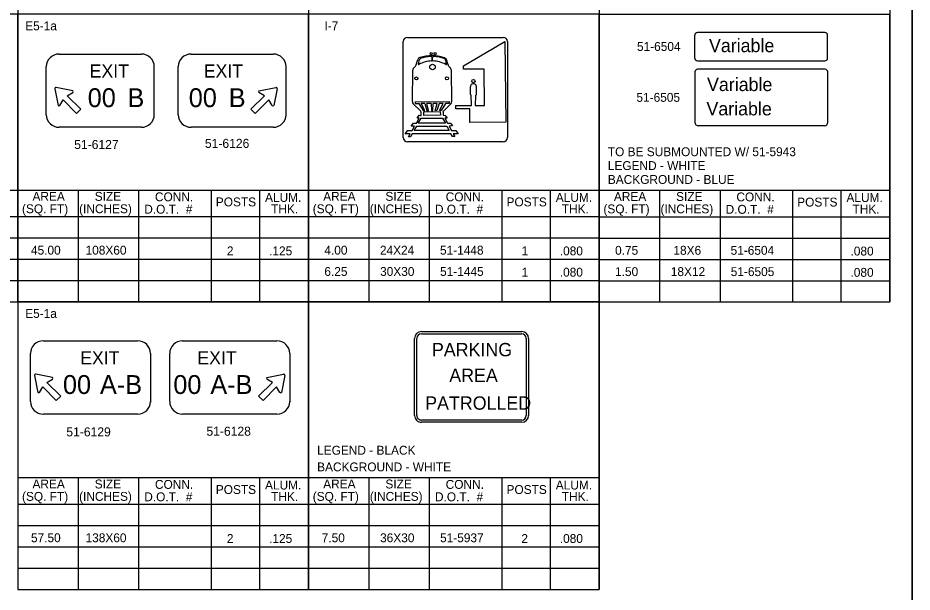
# Model space of a CAD drawing. Extents: x 0 to 2011, y -71 to 1183.
# Drawn here: x 947.8 to 1270, y 392.2 to 599.1 of the extents above; entities that cross this region are included whole.
import ezdxf

# ---------------------------------------------------------------- set-up
doc = ezdxf.new("R2010")
doc.units = 0
for name, color, linetype in [('CT_Border_Perimeter_Shape', 7, 'Continuous'), ('CT_Construction', 7, 'Continuous'), ('Level 1', 7, 'Continuous'), ('Level 2', 7, 'Continuous'), ('Level 5', 7, 'Continuous')]:
    doc.layers.add(name, color=color, linetype=linetype)

msp = doc.modelspace()

# ---------------------------------------------------------------- linework, layer by layer
at = {"layer": 'CT_Border_Perimeter_Shape'}
msp.add_lwpolyline([(0, -0.97), (1270, -0.97), (1270, 829.03), (0, 829.03)], close=True, dxfattribs=at)
at = {"layer": 'CT_Construction'}
msp.add_lwpolyline([(0, 829.03), (1270, 829.03), (1270, 59.03), (0, 59.03)], close=True, dxfattribs=at)
at = {"layer": 'Level 1'}
for p, q in [((1238.58, 593.82), (1192.65, 593.82)), ((1086.58, 556), (1086.58, 590.55)), ((1088.13, 592.1), (1122.68, 592.1)), ((1124.23, 590.55), (1124.23, 556)), ((1191.68, 584.63), (1191.68, 592.86)), ((1239.54, 584.63), (1239.54, 592.86)), ((962.59, 586.1), (992.27, 586.1)), ((1010.09, 586.1), (1039.77, 586.1)), ((1091.25, 582.22), (1091.84, 584.12)), ((1097.01, 583.77), (1097.02, 584.85)), ((1097.24, 583.77), (1097.23, 584.85)), ((1102.79, 582.19), (1102.2, 584.09)), ((1192.65, 583.67), (1238.58, 583.67)), ((958.02, 564.24), (958.02, 581.56)), ((996.94, 564.24), (996.94, 581.56)), ((1005.53, 564.24), (1005.53, 581.56)), ((1044.45, 564.24), (1044.45, 581.56)), ((1238.65, 580.59), (1192.72, 580.59)), ((1191.75, 579.62), (1191.75, 561.48)), ((1239.61, 561.48), (1239.61, 579.62)), ((961.05, 573.58), (962.26, 567.54)), ((967.57, 572.86), (961.54, 574.07)), ((1034.66, 572.86), (1040.69, 574.07)), ((1041.18, 573.58), (1039.98, 567.54)), ((965.54, 571.06), (967.57, 572.27)), ((970.5, 566.21), (965.54, 571.06)), ((1031.73, 566.21), (1036.7, 571.06)), ((1036.7, 571.06), (1034.66, 572.27)), ((962.85, 567.54), (964.06, 569.58)), ((964.06, 569.58), (968.9, 564.62)), ((1038.17, 569.58), (1033.33, 564.62)), ((1039.39, 567.54), (1038.17, 569.58)), ((1101.13, 565.56), (1103.78, 568.1)), ((968.9, 564.62), (970.5, 566.21)), ((1033.33, 564.62), (1031.73, 566.21)), ((1100.97, 565.12), (1101.01, 565.34)), ((1101.01, 565.34), (1101.13, 565.56)), ((992.27, 559.7), (962.69, 559.7)), ((1039.77, 559.7), (1010.2, 559.7)), ((1238.4, 560.27), (1192.96, 560.27)), ((1122.68, 554.45), (1088.13, 554.45)), ((1089.3, 556.23), (1088.5, 556.23)), ((1090.71, 455.87), (1090.71, 483.65)), ((1091.52, 455.87), (1091.52, 483.65)), ((1093.18, 486.11), (1129.32, 486.11)), ((1093.18, 485.31), (1129.32, 485.31)), ((1130.98, 483.65), (1130.98, 455.87)), ((1131.79, 483.65), (1131.79, 455.87)), ((956.86, 482.76), (986.55, 482.76)), ((956.86, 482.76), (990.9, 482.76)), ((1007.04, 482.76), (1036.73, 482.76)), ((1007.04, 482.76), (1041.09, 482.76)), ((952.3, 460.89), (952.3, 478.22)), ((995.57, 478.22), (995.57, 460.6)), ((1002.48, 460.89), (1002.48, 478.22)), ((1045.76, 478.22), (1045.76, 460.6)), ((960.29, 469.52), (954.25, 470.73)), ((1037.45, 469.52), (1043.49, 470.73)), ((953.76, 470.24), (954.97, 464.2)), ((958.25, 467.72), (960.29, 468.93)), ((963.21, 462.87), (958.25, 467.72)), ((1034.53, 462.87), (1039.49, 467.72)), ((1039.49, 467.72), (1037.45, 468.93)), ((1043.98, 470.24), (1042.77, 464.2)), ((955.56, 464.2), (956.77, 466.24)), ((956.77, 466.24), (961.62, 461.28)), ((1040.97, 466.24), (1036.12, 461.28)), ((1042.18, 464.2), (1040.97, 466.24)), ((961.62, 461.28), (963.21, 462.87)), ((1036.12, 461.28), (1034.53, 462.87)), ((990.9, 456.36), (956.97, 456.36)), ((1041.09, 456.36), (1007.15, 456.36)), ((1129.32, 454.21), (1093.18, 454.21)), ((1129.32, 453.41), (1093.18, 453.41))]:
    msp.add_line(p, q, dxfattribs=at)
for points in [[(1112.68, 571.19), (1112.57, 567.56), (1115.86, 567.56), (1115.79, 580.59), (1108.34, 580.58), (1108.37, 581.82), (1123.21, 590.65), (1123.57, 561.59)], [(1089.94, 568.98), (1090.05, 580.26)], [(1104.1, 568.95), (1103.99, 580.23)], [(1110.84, 571.52), (1110.85, 574.33)], [(1113, 571.48), (1112.99, 574.29)], [(1123.57, 561.59), (1110.63, 561.45), (1110.6, 566.39), (1105.57, 566.34), (1105.58, 567.49), (1111.29, 567.57), (1111.16, 571.24)], [(1088.5, 556.23), (1089.14, 557.31), (1087.38, 557.33), (1088.3, 558.52), (1089.85, 558.52), (1090.74, 560.13), (1089.54, 560.13), (1090.35, 561.21), (1091.42, 561.18), (1092.37, 562.95), (1091.67, 562.97), (1092.41, 564.01), (1092.89, 564), (1093.05, 564), (1093.07, 565.15), (1093.03, 565.37), (1092.91, 565.59), (1090.26, 568.13)], [(1090.98, 568.9), (1090.97, 568.27), (1092.2, 568.27)], [(1090.98, 568.9), (1103.14, 568.93), (1103.14, 568.32), (1101.91, 568.31)], [(1092.2, 568.27), (1093.82, 565.71), (1094.39, 565.71), (1093.08, 568.28)], [(1094.36, 568.28), (1093.08, 568.28)], [(1094.36, 568.28), (1095.2, 565.71), (1095.79, 565.71), (1095.09, 568.28)], [(1096.75, 568.29), (1095.09, 568.28)], [(1096.75, 568.29), (1096.81, 565.71), (1097.35, 565.71), (1097.43, 568.29)], [(1098.82, 568.3), (1097.43, 568.3)], [(1099.55, 568.3), (1098.7, 565.7), (1098.11, 565.7), (1098.82, 568.3)], [(1101.03, 568.31), (1099.55, 568.3)], [(1101.91, 568.31), (1100.28, 565.73), (1099.71, 565.73), (1101.03, 568.31)], [(1100.97, 565.12), (1100.98, 564.01), (1101.75, 564), (1102.41, 563.01), (1101.59, 563.01), (1102.55, 561.19), (1103.69, 561.2), (1104.38, 560.19), (1103.17, 560.13), (1104.04, 558.49), (1105.59, 558.51), (1106.39, 557.39), (1104.66, 557.39), (1105.21, 556.34), (1104.38, 556.35), (1103.83, 557.36), (1089.91, 557.33), (1089.3, 556.23)], [(1094.11, 565.31), (1099.99, 565.34), (1100.02, 564.02), (1094.1, 563.99), (1094.11, 565.31)], [(1093.07, 562.95), (1100.77, 563.02), (1101.83, 561.23), (1092.05, 561.18), (1093.14, 562.93)], [(1091.49, 560.11), (1102.35, 560.15), (1103.2, 558.54), (1090.61, 558.53), (1091.56, 560.09)]]:
    msp.add_lwpolyline(points, dxfattribs=at)
for centre, radius in [((1096.69, 586.21), 0.407), ((1098.13, 586.22), 0.407), ((1097.19, 581.41), 1), ((1091.36, 577.28), 0.535), ((1102.4, 577.34), 0.535), ((1111.9, 576.36), 0.598)]:
    msp.add_circle(centre, radius, dxfattribs=at)
for centre, radius, start, end in [((1192.65, 592.86), 0.968, 90, 180), ((1238.58, 592.86), 0.968, 360, 90), ((1088.13, 590.55), 1.55, 90, 180), ((1122.68, 590.55), 1.55, 0, 90), ((1092.99, 583.55), 1.28, 104.4029, 153.5069), ((1099.22, 581.59), 7.21, 160.8398, 173.2704), ((1097.46, 572.25), 11.36, 92.9416, 117.1252), ((1093.01, 583.89), 0.6, 103.6949, 173.6857), ((1096.98, 571.86), 13.63, 71.1878, 108.433), ((1096.67, 574.66), 10.53, 90.8903, 111.1999), ((1096.54, 584.68), 0.506, 19.0492, 93.9205), ((1096.84, 583.76), 0.173, 283.9226, 2.456), ((1097.71, 584.68), 0.506, 86.0795, 160.9508), ((1097.41, 583.76), 0.173, 177.544, 256.0774), ((1096.79, 572.25), 11.36, 62.8748, 87.0584), ((1097.58, 574.66), 10.53, 68.8001, 89.1097), ((1101.06, 583.52), 1.28, 26.4931, 75.5971), ((1101.25, 583.89), 0.6, 6.3143, 76.3051), ((1095.04, 581.59), 7.21, 6.7296, 19.1602), ((1192.65, 584.63), 0.968, 180, 270), ((1238.58, 584.63), 0.968, 270, 0), ((1091.47, 580.13), 1.43, 126.0727, 174.8195), ((1089.52, 582.7), 1.8, 308.031, 344.3003), ((1092.19, 582.45), 0.128, 182.8654, 318.1939), ((1102.07, 582.45), 0.128, 221.806, 357.1346), ((1104.52, 582.67), 1.8, 195.6997, 231.969), ((1102.58, 580.11), 1.43, 5.1805, 53.9273), ((1192.72, 579.62), 0.968, 90, 180), ((1238.64, 579.62), 0.968, 360, 90), ((961.46, 573.66), 0.418, 78.7145, 191.291), ((1040.77, 573.66), 0.418, 348.709, 101.2855), ((1111.92, 574.33), 1.07, 357.9657, 179.6228), ((967.28, 572.57), 0.418, 315, 45), ((1034.95, 572.57), 0.418, 135, 225), ((1111.19, 571.6), 0.362, 191.7388, 264.7446), ((1112.65, 571.55), 0.362, 275.2554, 348.2612), ((962.55, 567.84), 0.418, 225, 315), ((1039.68, 567.84), 0.418, 225, 315), ((1091.23, 568.97), 1.28, 179.499, 221.231), ((1102.82, 568.94), 1.28, 318.769, 0.501), ((1192.96, 561.48), 1.21, 180, 270), ((1238.4, 561.48), 1.21, 270, 360), ((1088.13, 556), 1.55, 180, 270), ((1122.68, 556), 1.55, 270, 0), ((1093.18, 483.65), 2.47, 90, 180), ((1093.18, 483.65), 1.66, 90, 180), ((1129.32, 483.65), 2.47, 0.0023, 89.9991), ((1129.32, 483.65), 1.66, 0.0023, 89.9987), ((954.17, 470.32), 0.418, 78.7145, 191.291), ((1043.57, 470.32), 0.418, 348.709, 101.2855), ((959.99, 469.23), 0.418, 315, 45), ((1037.75, 469.23), 0.418, 135, 225), ((955.26, 464.5), 0.418, 225, 315), ((1042.47, 464.5), 0.418, 225, 315), ((1093.18, 455.87), 2.47, 179.998, 270), ((1089.87, 455.87), 0.84, 359.998, 0), ((1093.18, 455.87), 1.66, 179.998, 270), ((1089.87, 455.87), 1.64, 359.998, 0), ((1129.32, 455.87), 1.66, 270, 360), ((1129.32, 455.87), 2.47, 270, 360), ((1093.18, 452.57), 1.64, 90, 90.0015), ((1093.18, 452.57), 0.84, 90, 90.0015)]:
    msp.add_arc(centre, radius, start, end, dxfattribs=at)
for centre, major_axis, ratio, start_param, end_param in [((962.69, 581.56), (-4.67, 0), 0.970874, 4.712389, 6.283185), ((992.27, 581.56), (-4.67, 0), 0.97089, 3.141593, 4.712389), ((1010.2, 581.56), (-4.67, 0), 0.970874, 4.712389, 6.283185), ((1039.77, 581.56), (-4.67, 0), 0.97089, 3.141593, 4.712389), ((962.69, 564.24), (4.67, 0), 0.970874, 3.141593, 4.712389), ((992.27, 564.24), (4.67, 0), 0.970874, 4.712389, 6.283185), ((1010.2, 564.24), (4.67, 0), 0.970874, 3.141593, 4.712389), ((1039.77, 564.24), (4.67, 0), 0.970874, 4.712389, 6.283185), ((956.97, 478.22), (-4.67, 0), 0.970874, 4.712389, 6.283185), ((990.9, 478.22), (-4.67, 0), 0.97089, 3.141593, 4.712389), ((1007.15, 478.22), (-4.67, 0), 0.970874, 4.712389, 6.283185), ((1041.09, 478.22), (-4.67, 0), 0.97089, 3.141593, 4.712389), ((956.97, 460.89), (4.67, 0), 0.970874, 3.141593, 4.712389), ((990.9, 460.89), (4.67, 0), 0.970874, 4.712389, 6.283185), ((1007.15, 460.89), (4.67, 0), 0.970874, 3.141593, 4.712389), ((1041.09, 460.89), (4.67, 0), 0.970874, 4.712389, 6.283185)]:
    msp.add_ellipse(centre, major_axis=major_axis, ratio=ratio, start_param=start_param, end_param=end_param, dxfattribs=at)
at = {"layer": 'Level 2'}
for p, q in [((843.04, 537.09), (947.79, 537.09)), ((947.79, 537.09), (1052.53, 537.09)), ((969.54, 537.09), (969.54, 496.81)), ((991.29, 537.09), (991.29, 496.81)), ((1017.39, 537.09), (1017.39, 496.81)), ((1034.79, 537.09), (1034.79, 496.81)), ((1052.53, 537.09), (1157.28, 537.09)), ((1074.28, 537.09), (1074.28, 496.81)), ((1096.03, 537.09), (1096.03, 496.81)), ((1122.13, 537.09), (1122.13, 496.81)), ((1139.53, 537.09), (1139.53, 496.81)), ((1157.28, 537.03), (1262.03, 537.03)), ((1179.03, 537.03), (1179.03, 496.76)), ((1200.78, 537.03), (1200.78, 496.76)), ((1226.88, 537.03), (1226.88, 496.76)), ((1244.28, 537.03), (1244.28, 496.76)), ((843.04, 527.5), (947.79, 527.5)), ((947.79, 527.5), (1052.53, 527.5)), ((1052.53, 527.5), (1157.28, 527.5)), ((1157.28, 527.44), (1262.03, 527.44)), ((843.04, 519.83), (947.79, 519.83)), ((947.79, 519.83), (1052.53, 519.83)), ((1052.53, 519.83), (1157.28, 519.83)), ((1157.28, 519.77), (1262.03, 519.77)), ((843.04, 512.16), (947.79, 512.16)), ((947.79, 512.16), (1052.53, 512.16)), ((1052.53, 512.16), (1157.28, 512.16)), ((1157.28, 512.1), (1262.03, 512.1)), ((843.04, 504.48), (947.79, 504.48)), ((947.79, 504.48), (1052.53, 504.48)), ((1052.53, 504.48), (1157.28, 504.48)), ((1157.28, 504.43), (1262.03, 504.43)), ((947.79, 433.47), (1052.53, 433.47)), ((969.54, 433.47), (969.54, 393.19)), ((991.29, 433.47), (991.29, 393.19)), ((1017.39, 433.47), (1017.39, 393.19)), ((1034.79, 433.47), (1034.79, 393.19)), ((1052.53, 433.47), (1157.28, 433.47)), ((1074.28, 433.47), (1074.28, 393.19)), ((1096.03, 433.47), (1096.03, 393.19)), ((1122.13, 433.47), (1122.13, 393.19)), ((1139.53, 433.47), (1139.53, 393.19)), ((947.79, 423.88), (1052.53, 423.88)), ((1052.53, 423.88), (1157.28, 423.88)), ((947.79, 416.2), (1052.53, 416.2)), ((1052.53, 416.2), (1157.28, 416.2)), ((947.79, 408.53), (1052.53, 408.53)), ((1052.53, 408.53), (1157.28, 408.53)), ((947.79, 400.86), (1052.53, 400.86)), ((1052.53, 400.86), (1157.28, 400.86))]:
    msp.add_line(p, q, dxfattribs=at)
for points in [[(947.79, 600.44), (843.04, 600.44), (843.04, 496.81), (947.79, 496.81)], [(1052.53, 600.44), (947.79, 600.44), (947.79, 496.81), (1052.53, 496.81)], [(1157.28, 600.44), (1052.53, 600.44), (1052.53, 496.81), (1157.28, 496.81)], [(1262.03, 600.38), (1157.28, 600.38), (1157.28, 496.76), (1262.03, 496.76)], [(1052.53, 496.81), (947.79, 496.81), (947.79, 393.19), (1052.53, 393.19)], [(1157.28, 496.81), (1052.53, 496.81), (1052.53, 393.19), (1157.28, 393.19)]]:
    msp.add_lwpolyline(points, close=True, dxfattribs=at)
at = {"layer": 'Level 5'}
for p, q in [((947.79, 830), (947.79, 496.81)), ((1052.53, 830), (1052.53, 393.19)), ((1157.28, 830), (1157.28, 393.19)), ((1262.03, 830), (1262.03, 496.76)), ((1157.28, 722.51), (1157.28, 496.61))]:
    msp.add_line(p, q, dxfattribs=at)

# ---------------------------------------------------------------- texts
at = {"layer": 'Level 1'}
for s, p in [('51-6127', (968.08, 551.86)), ('51-6126', (1015.17, 552.26)), ('51-6129', (965.24, 448.33)), ('51-6128', (1015.73, 448.57))]:
    msp.add_text(s, height=3.264, dxfattribs=at).set_placement(p)
at = {"layer": 'Level 2'}
for s, height, p in [('E5-1a', 3.2, (950.42, 594.64)), ('I-7', 3.2, (1058.24, 594.64)), ('51-6504', 3.2, (1170.86, 587.21)), ('Variable', 4.8, (1196.8, 586.76)), ('EXIT', 4.763, (973.64, 577.6)), ('EXIT', 4.763, (1014.76, 577.6)), ('Variable', 4.8, (1196.1, 572.74)), ('00', 6.804, (972.95, 566.95)), ('B', 6.8, (987.27, 566.95)), ('00', 6.804, (1009.36, 566.95)), ('B', 6.8, (1023.77, 566.95)), ('51-6505', 3.2, (1170.67, 568.88)), ('Variable', 4.8, (1195.89, 563.99)), ('TO BE SUBMOUNTED W/ 51-5943', 3.2, (1160.36, 549.29)), ('LEGEND - WHITE', 3.2, (1160.36, 544.29)), ('BACKGROUND - BLUE', 3.2, (1160.36, 539.29)), ('AREA', 3.2, (953.05, 533.21)), ('SIZE', 3.2, (975.47, 533.21)), ('CONN.', 3.2, (997.18, 533.05)), ('ALUM.', 3.2, (1036.85, 532.83)), ('AREA', 3.2, (1057.8, 533.21)), ('SIZE', 3.2, (1080.21, 533.21)), ('CONN.', 3.2, (1101.93, 533.05)), ('ALUM.', 3.2, (1141.6, 532.83)), ('AREA', 3.2, (1162.55, 533.15)), ('SIZE', 3.2, (1184.96, 533.15)), ('CONN.', 3.2, (1206.68, 533)), ('ALUM.', 3.2, (1246.34, 532.77)), ('(SQ. FT)', 3.2, (949.27, 528.74)), ('(INCHES)', 3.2, (969.84, 528.74)), ('D.O.T.  #', 3.2, (993.32, 528.58)), ('POSTS', 3.2, (1019.11, 531.2)), ('THK.', 3.2, (1039.03, 528.69)), ('(SQ. FT)', 3.2, (1054.02, 528.74)), ('(INCHES)', 3.2, (1074.58, 528.74)), ('D.O.T.  #', 3.2, (1098.07, 528.58)), ('POSTS', 3.2, (1123.86, 531.2)), ('THK.', 3.2, (1143.77, 528.69)), ('(SQ. FT)', 3.2, (1158.77, 528.68)), ('(INCHES)', 3.2, (1179.33, 528.68)), ('D.O.T.  #', 3.2, (1202.81, 528.53)), ('POSTS', 3.2, (1228.6, 531.15)), ('THK.', 3.2, (1248.52, 528.63)), ('E5-1a', 3.2, (950.42, 491.02)), ('PARKING', 4.8, (1096.98, 477.19)), ('EXIT', 4.763, (970.23, 474.26)), ('EXIT', 4.763, (1012.45, 474.26)), ('00', 6.804, (964.02, 463.61)), ('00', 6.804, (1003.8, 463.61)), ('AREA', 4.8, (1103.23, 467.93)), ('A-B', 6.804, (977.36, 463.61)), ('A-B', 6.804, (1017.14, 463.61)), ('PATROLLED', 4.8, (1094.55, 457.95)), ('LEGEND - BLACK', 3.2, (1055.61, 441.73)), ('BACKGROUND - WHITE', 3.2, (1055.61, 435.73)), ('AREA', 3.2, (953.05, 429.58)), ('SIZE', 3.2, (975.47, 429.58)), ('CONN.', 3.2, (997.18, 429.43)), ('ALUM.', 3.2, (1036.85, 429.2)), ('AREA', 3.2, (1057.8, 429.58)), ('SIZE', 3.2, (1080.21, 429.58)), ('CONN.', 3.2, (1101.93, 429.43)), ('ALUM.', 3.2, (1141.6, 429.2)), ('POSTS', 3.2, (1019.11, 427.58)), ('POSTS', 3.2, (1123.86, 427.58)), ('(SQ. FT)', 3.2, (949.27, 425.11)), ('(INCHES)', 3.2, (969.84, 425.11)), ('D.O.T.  #', 3.2, (993.32, 424.96)), ('THK.', 3.2, (1039.03, 425.06)), ('(SQ. FT)', 3.2, (1054.02, 425.11)), ('(INCHES)', 3.2, (1074.58, 425.11)), ('D.O.T.  #', 3.2, (1098.07, 424.96)), ('THK.', 3.2, (1143.77, 425.06))]:
    msp.add_text(s, height=height, dxfattribs=at).set_placement(p)
at = {"layer": 'Level 5'}
for s, p in [('45.00', (952.5, 513.82)), ('108X60', (972.17, 513.82)), ('2 ', (1023.08, 513.56)), ('.125', (1038.31, 513.56)), (' 4.00', (1057.03, 513.82)), ('24X24', (1078.24, 513.82)), ('51-1448', (1099.88, 513.82)), ('1', (1129.27, 513.56)), ('.080', (1143.05, 513.56)), (' 0.75', (1161.78, 513.77)), (' 18X6', (1182.8, 513.77)), ('51-6504', (1204.59, 513.77)), ('.080', (1247.8, 513.5)), (' 6.25', (1057.03, 506.15)), ('30X30', (1078.3, 506.15)), ('51-1445', (1099.91, 506.15)), ('.080', (1143.05, 505.89)), (' 1.50', (1161.78, 506.09)), ('18X12', (1183.05, 506.09)), ('51-6505', (1204.65, 506.09)), ('1', (1129.27, 505.89)), ('.080', (1247.8, 505.83)), ('57.50', (952.5, 410.2)), ('138X60', (972.17, 410.2)), ('2 ', (1023.08, 409.94)), ('.125', (1038.31, 409.94)), ('7.50 ', (1057.26, 410.2)), ('36X30', (1078.3, 410.2)), ('51-5937', (1099.91, 410.2)), ('2', (1129.21, 409.94)), ('.080', (1143.05, 409.94))]:
    msp.add_text(s, height=3.2, dxfattribs=at).set_placement(p)

doc.saveas('drawing.dxf')
